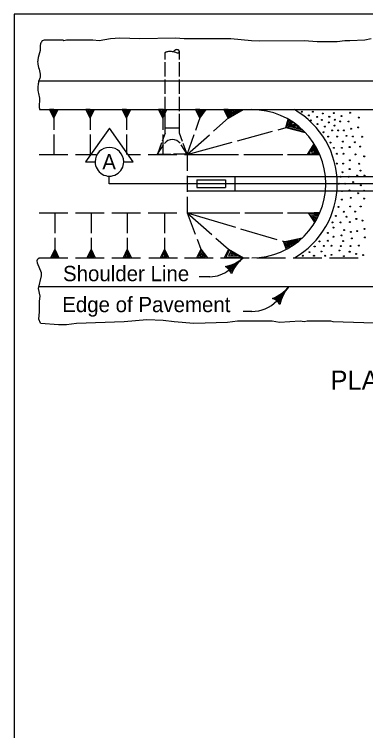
# Model space of a CAD drawing. Extents: x -772 to 772, y -957 to 657.
# Drawn here: x -772 to -405, y -91 to 657 of the extents above; entities that cross this region are included whole.
import ezdxf

# ---------------------------------------------------------------- set-up
doc = ezdxf.new("R2010")
doc.units = 0
for name, color, linetype in [('Default', 7, 'Continuous'), ('dsnCellElements', 7, 'Continuous'), ('dsnStdSection', 7, 'Continuous'), ('Level 2', 7, 'Continuous'), ('Level 3', 7, 'Continuous'), ('Level 4', 7, 'Continuous')]:
    doc.layers.add(name, color=color, linetype=linetype)

msp = doc.modelspace()

# ---------------------------------------------------------------- linework, layer by layer
at = {"layer": 'Default'}
msp.add_line((-746.08, 557.84), (-61.91, 557.84), dxfattribs=at)
for radius, start, end in [(77.5, 0, 90), (89.5, 0, 59.98813), (77.5, 270, 0), (89.5, 300.01187, 360)]:
    msp.add_arc((-524.08, 480.34), radius, start, end, dxfattribs=at)
at = {"layer": 'dsnCellElements'}
msp.add_lwpolyline([(-772.5, 657.5), (-772.5, -657.5), (772.5, -657.5), (772.5, 657.5), (-772.5, 657.5)], dxfattribs=at)
at = {"layer": 'dsnStdSection'}
msp.add_lwpolyline([(-657.96, 503.34), (-647.96, 503.34), (-672.96, 538.34), (-697.96, 503.34), (-687.96, 503.34)], dxfattribs=at)
for start, end in [(0.00083, 179.99917), (179.99917, 0.00083)]:
    msp.add_arc((-672.96, 503.34), 15, start, end, dxfattribs=at)
at = {"layer": 'Level 2'}
for p, q in [((-742.99, 630.31), (-742.83, 630.31)), ((-614.65, 617.56), (-614.79, 617.46)), ((-614.79, 610.4), (-614.79, 617.46)), ((-599.79, 617.83), (-599.78, 618.68)), ((-599.79, 610.4), (-599.79, 617.83)), ((-599.78, 618.71), (-599.78, 618.68)), ((-614.79, 592.4), (-614.79, 607.4)), ((-599.79, 592.4), (-599.79, 607.4)), ((-614.79, 592.4), (-614.79, 592.4)), ((-599.79, 592.4), (-599.79, 592.4)), ((-746.98, 588.25), (-747.03, 587.84)), ((-747.03, 587.84), (-62.6, 587.84)), ((-746.86, 587.68), (-747.03, 587.84)), ((-614.79, 574.4), (-614.79, 589.4)), ((-599.79, 574.4), (-599.79, 589.4)), ((-614.79, 556.4), (-614.79, 571.4)), ((-614.79, 571.4), (-614.79, 571.4)), ((-599.79, 556.4), (-599.79, 571.4)), ((-746.11, 557.99), (-746.08, 557.84)), ((-746.08, 557.84), (-716.58, 557.84)), ((-731.22, 557.84), (-735.72, 557.84)), ((-731.22, 548.84), (-735.72, 557.84)), ((-734.68, 557.44), (-731.19, 550.37)), ((-727.79, 557.3), (-733.59, 557.39)), ((-733.59, 557.39), (-731, 551.69)), ((-729.16, 556.35), (-732.27, 556.64)), ((-732.27, 556.64), (-731.05, 553.29)), ((-730.1, 555.51), (-731.42, 555.84)), ((-731.42, 555.84), (-731, 554.85)), ((-731.22, 557.84), (-731.22, 536.84)), ((-731.22, 548.84), (-731.22, 557.84)), ((-731.22, 557.84), (-726.72, 557.84)), ((-731.22, 548.84), (-726.72, 557.84)), ((-731.19, 550.37), (-727.79, 557.3)), ((-731.05, 553.29), (-730.1, 555.51)), ((-731, 551.69), (-729.16, 556.35)), ((-708.58, 557.84), (-678.58, 557.84)), ((-693.22, 557.84), (-697.72, 557.84)), ((-693.22, 548.84), (-697.72, 557.84)), ((-696.46, 557.27), (-693.21, 550.34)), ((-689.86, 557.18), (-695.19, 557.13)), ((-695.19, 557.13), (-693.21, 552.32)), ((-691.23, 556.43), (-693.87, 556.28)), ((-693.87, 556.28), (-693.16, 553.97)), ((-693.22, 557.84), (-693.22, 536.84)), ((-693.22, 548.84), (-693.22, 557.84)), ((-693.22, 557.84), (-688.72, 557.84)), ((-693.22, 548.84), (-688.72, 557.84)), ((-693.21, 550.34), (-689.86, 557.18)), ((-693.21, 552.32), (-691.23, 556.43)), ((-693.16, 553.97), (-692.41, 555.48)), ((-670.58, 557.84), (-640.58, 557.84)), ((-655.23, 557.84), (-659.73, 557.84)), ((-655.23, 548.84), (-659.73, 557.84)), ((-658.49, 557.2), (-655.26, 550.32)), ((-652.1, 557.16), (-657.33, 557.16)), ((-657.33, 557.16), (-655.3, 552.21)), ((-653.49, 556.4), (-656.01, 556.28)), ((-656.01, 556.28), (-655.21, 554.04)), ((-655.3, 552.21), (-653.49, 556.4)), ((-655.26, 550.32), (-652.1, 557.16)), ((-655.23, 557.84), (-655.23, 536.84)), ((-655.23, 548.84), (-655.23, 557.84)), ((-655.23, 557.84), (-650.73, 557.84)), ((-655.23, 548.84), (-650.73, 557.84)), ((-655.21, 554.04), (-654.43, 555.74)), ((-632.58, 557.84), (-602.58, 557.84)), ((-621.89, 557.84), (-610.2, 557.84)), ((-617.23, 557.84), (-621.73, 557.84)), ((-617.23, 548.84), (-621.73, 557.84)), ((-616.24, 557.84), (-620.74, 557.84)), ((-620.64, 557.28), (-617.25, 550.3)), ((-613.85, 557.23), (-619.51, 557.09)), ((-619.51, 557.09), (-617.29, 551.81)), ((-615.12, 556.33), (-617.95, 556.14)), ((-617.95, 556.14), (-617.15, 553.46)), ((-617.29, 551.81), (-615.12, 556.33)), ((-617.25, 550.3), (-613.85, 557.23)), ((-617.23, 557.84), (-617.23, 536.84)), ((-617.23, 548.84), (-617.23, 557.84)), ((-617.23, 557.84), (-612.73, 557.84)), ((-617.23, 548.84), (-612.73, 557.84)), ((-617.15, 553.46), (-616.54, 555.29)), ((-616.54, 555.29), (-616.3, 555.72)), ((-616.24, 557.84), (-611.74, 557.84)), ((-614.79, 556.4), (-614.79, 556.4)), ((-594.58, 557.84), (-564.58, 557.84)), ((-578.41, 557.84), (-582.91, 557.84)), ((-578.41, 548.84), (-582.91, 557.84)), ((-582.7, 536.45), (-575.29, 557.84)), ((-581.48, 557.16), (-578.37, 550.56)), ((-576.58, 556.88), (-579.97, 557.02)), ((-579.97, 557.02), (-578.56, 553.1)), ((-577.61, 556.03), (-578.75, 556.03)), ((-578.75, 556.03), (-578.6, 554.85)), ((-578.56, 553.1), (-577.61, 556.03)), ((-578.41, 557.84), (-573.91, 557.84)), ((-578.41, 548.84), (-571.62, 557.84)), ((-578.37, 550.56), (-576.58, 556.88)), ((-576.77, 551.92), (-574.74, 556.92)), ((-573.42, 556.88), (-575.63, 553.2)), ((-574.74, 556.92), (-573.42, 556.88)), ((-563.97, 535.35), (-538.62, 557.84)), ((-556.58, 557.84), (-526.58, 557.84)), ((-548.76, 557.84), (-553.26, 557.84)), ((-548.76, 548.84), (-553.26, 557.84)), ((-552.18, 557.23), (-548.64, 549.87)), ((-540.43, 557.28), (-550.95, 557.18)), ((-550.95, 557.18), (-548.5, 551.53)), ((-542.6, 556.48), (-549.53, 556.15)), ((-549.53, 556.15), (-548.17, 553.08)), ((-548.76, 557.84), (-544.26, 557.84)), ((-548.76, 548.84), (-533.1, 557.84)), ((-548.64, 549.87), (-540.43, 557.28)), ((-548.5, 551.53), (-542.6, 556.48)), ((-544.87, 555.63), (-548.26, 555.25)), ((-548.26, 555.25), (-547.84, 554.21)), ((-548.17, 553.08), (-544.87, 555.63)), ((-547.84, 554.21), (-546.71, 554.83)), ((-543.4, 552.47), (-538.36, 557.04)), ((-535.58, 557.18), (-540.34, 554.31)), ((-540.34, 554.31), (-538.17, 556.38)), ((-538.36, 557.04), (-535.58, 557.18)), ((-518.58, 557.84), (-488.58, 557.84)), ((-480.58, 557.84), (-450.58, 557.84)), ((-442.58, 557.84), (-412.58, 557.84)), ((-614.79, 538.4), (-614.79, 553.4)), ((-614.79, 553.4), (-614.79, 553.4)), ((-599.79, 538.4), (-599.79, 553.4)), ((-488.42, 539.18), (-485.93, 547.8)), ((-487.3, 539.49), (-484.86, 547.19)), ((-496.52, 536.91), (-477.35, 542.17)), ((-488.42, 539.18), (-468.1, 533.94)), ((-487.3, 539.49), (-469.19, 535.05)), ((-483.9, 546.61), (-485.75, 540.7)), ((-485.75, 540.7), (-478.4, 542.87)), ((-482.92, 545.04), (-484.15, 542.02)), ((-484.15, 542.02), (-481.51, 543.25)), ((-483.3, 539.57), (-476.7, 541.55)), ((-478.4, 542.87), (-482.92, 545.04)), ((-481.51, 543.25), (-482.31, 543.77)), ((-481.04, 539.29), (-476.6, 540.14)), ((-472.08, 536.74), (-481.04, 539.29)), ((-476.7, 541.55), (-472.08, 536.74)), ((-476.6, 540.14), (-474.81, 538.63)), ((-731.22, 531.84), (-731.22, 510.84)), ((-693.22, 531.84), (-693.22, 510.84)), ((-655.23, 531.84), (-655.23, 510.84)), ((-614.79, 533.4), (-617.81, 525.08)), ((-617.23, 531.84), (-617.23, 510.84)), ((-599.79, 538.4), (-614.79, 538.4)), ((-614.79, 533.4), (-614.79, 538.4)), ((-599.79, 533.4), (-599.79, 538.4)), ((-596.57, 524.56), (-599.79, 533.4)), ((-591.58, 510.84), (-584.3, 531.85)), ((-538.86, 525.3), (-502.22, 535.35)), ((-474.81, 538.63), (-476.65, 539.05)), ((-591.58, 510.84), (-568.21, 531.58)), ((-618.57, 522.99), (-622.83, 511.3)), ((-622.83, 511.3), (-616.48, 520.98)), ((-591.75, 511.3), (-597.77, 520.98)), ((-591.75, 511.3), (-595.84, 522.54)), ((-591.58, 510.84), (-544.58, 523.73)), ((-465.63, 510.95), (-458.89, 522.06)), ((-464.31, 511.68), (-458.29, 520.98)), ((-458.13, 519.68), (-461.73, 513.91)), ((-461.73, 513.91), (-456.79, 516.87)), ((-457.74, 518.39), (-459.38, 516.29)), ((-459.38, 516.29), (-457.86, 517.24)), ((-456.79, 516.87), (-457.74, 518.39)), ((-746.58, 510.84), (-716.58, 510.84)), ((-708.58, 510.84), (-692.6, 510.84)), ((-699.77, 510.84), (-686.83, 510.84)), ((-653.31, 510.84), (-640.58, 510.84)), ((-632.58, 510.84), (-602.58, 510.84)), ((-622.83, 511.3), (-608.83, 511.3)), ((-591.75, 511.3), (-605.75, 511.3)), ((-594.58, 510.84), (-591.58, 510.84)), ((-594.58, 510.84), (-591.58, 510.84)), ((-591.58, 510.84), (-591.58, 493.84)), ((-591.58, 510.84), (-537.9, 510.84)), ((-532.37, 510.84), (-491.68, 510.84)), ((-486.63, 510.84), (-452.83, 510.84)), ((-465.63, 510.95), (-452.62, 510.75)), ((-464.31, 511.68), (-453.22, 511.83)), ((-461.17, 512.71), (-454.34, 512.83)), ((-455.88, 515.43), (-459.02, 513.69)), ((-459.02, 513.69), (-455.81, 513.74)), ((-455.81, 513.74), (-456.14, 514.53)), ((-454.34, 512.83), (-455.88, 515.43)), ((-673.22, 480.34), (-673.22, 488.34)), ((-591.58, 488.84), (-591.58, 471.84)), ((-117.94, 480.34), (-673.22, 480.34)), ((-591.58, 466.84), (-591.58, 449.84)), ((-746.58, 449.84), (-716.58, 449.84)), ((-730.24, 449.84), (-730.24, 428.84)), ((-708.58, 449.84), (-678.58, 449.84)), ((-692.24, 449.84), (-692.24, 428.84)), ((-670.58, 449.84), (-640.58, 449.84)), ((-654.24, 449.84), (-654.24, 428.84)), ((-632.58, 449.84), (-602.58, 449.84)), ((-615.25, 449.84), (-615.25, 428.84)), ((-591.58, 449.84), (-536.54, 449.84)), ((-591.58, 449.84), (-541.02, 434.94)), ((-591.58, 449.84), (-565.82, 427.17)), ((-591.58, 449.84), (-583.18, 427.55)), ((-531.41, 449.84), (-491.68, 449.84)), ((-486.47, 449.84), (-452.83, 449.84)), ((-465.05, 449.83), (-452.54, 450.76)), ((-465.05, 449.83), (-457.93, 439.7)), ((-464.15, 449.39), (-452.97, 449.86)), ((-464.15, 449.39), (-457.59, 440.39)), ((-461.64, 447.51), (-456.09, 444.7)), ((-461.36, 448.74), (-454.06, 448.85)), ((-457.45, 441.9), (-460.49, 446.01)), ((-460.49, 446.01), (-457.1, 444.35)), ((-459.24, 447.71), (-455.53, 448)), ((-455.51, 446.31), (-459.24, 447.71)), ((-457.1, 444.35), (-457.47, 443.38)), ((-456.09, 444.7), (-457.45, 441.9)), ((-455.53, 448), (-455.78, 447.28)), ((-454.06, 448.85), (-455.51, 446.31)), ((-535.85, 433.42), (-497.63, 422.15)), ((-730.24, 423.84), (-730.24, 402.84)), ((-692.24, 423.84), (-692.24, 402.84)), ((-654.24, 423.84), (-654.24, 402.84)), ((-615.25, 423.84), (-615.25, 402.84)), ((-581.28, 422.52), (-577.26, 411.84)), ((-561.5, 423.37), (-548.4, 411.84)), ((-492.21, 420.55), (-479.65, 416.85)), ((-490.65, 419.83), (-471.11, 423.77)), ((-490.65, 419.83), (-488.08, 411.71)), ((-487.11, 419.73), (-472.78, 423.03)), ((-485.32, 419.16), (-475.42, 421.52)), ((-481.45, 419.16), (-478.43, 419.92)), ((-475.79, 419.73), (-479.47, 417.56)), ((-475.42, 421.52), (-479.19, 418.5)), ((-472.78, 423.03), (-475.79, 419.73)), ((-489.09, 418.6), (-487.86, 413.79)), ((-487.86, 413.79), (-481.64, 416.24)), ((-481.64, 416.24), (-487.68, 417.84)), ((-487.68, 417.84), (-487.11, 415.2)), ((-487.11, 415.2), (-484.28, 416.24)), ((-484.28, 416.24), (-486.26, 416.52)), ((-479.47, 417.56), (-485.32, 419.16)), ((-479.19, 418.5), (-481.45, 419.16)), ((-730.24, 411.84), (-734.74, 402.84)), ((-730.17, 410.03), (-733.19, 403.52)), ((-729.6, 408.99), (-731.77, 404.46)), ((-731.77, 404.46), (-728.66, 404.28)), ((-729.56, 406.77), (-730.78, 405.08)), ((-730.78, 405.08), (-729.51, 404.89)), ((-730.24, 411.84), (-730.24, 402.84)), ((-730.24, 411.84), (-725.74, 402.84)), ((-727.29, 403.47), (-729.6, 408.99)), ((-728.66, 404.28), (-729.56, 406.77)), ((-692.24, 411.84), (-696.74, 402.84)), ((-692.21, 410.55), (-695.42, 403.52)), ((-691.69, 409.18), (-693.91, 404.37)), ((-693.91, 404.37), (-690.61, 404.42)), ((-691.6, 407.29), (-692.78, 405.03)), ((-692.78, 405.03), (-691.5, 405.08)), ((-692.24, 411.84), (-692.24, 402.84)), ((-692.24, 411.84), (-687.74, 402.84)), ((-692.24, 411.02), (-692.24, 402.84)), ((-689.19, 403.57), (-691.69, 409.18)), ((-690.61, 404.42), (-691.6, 407.29)), ((-691.5, 405.08), (-691.55, 405.6)), ((-654.24, 411.84), (-658.74, 402.84)), ((-654.42, 409.86), (-656.97, 403.92)), ((-653.85, 408.54), (-655.08, 405.24)), ((-655.08, 405.24), (-652.72, 404.86)), ((-654.24, 411.84), (-654.24, 402.84)), ((-654.24, 411.84), (-649.74, 402.84)), ((-654.24, 411.02), (-654.24, 402.84)), ((-651.21, 403.92), (-653.85, 408.54)), ((-653.67, 406.75), (-653.85, 405.71)), ((-652.72, 404.86), (-653.67, 406.75)), ((-615.25, 411.84), (-619.75, 402.84)), ((-615.43, 409.86), (-617.98, 403.92)), ((-614.87, 408.54), (-616.09, 405.24)), ((-616.09, 405.24), (-613.74, 404.86)), ((-615.25, 411.84), (-615.25, 402.84)), ((-615.25, 411.84), (-610.75, 402.84)), ((-615.25, 411.02), (-615.25, 402.84)), ((-612.23, 403.92), (-614.87, 408.54)), ((-614.68, 406.75), (-614.87, 405.71)), ((-613.74, 404.86), (-614.68, 406.75)), ((-577.26, 411.84), (-581.76, 402.84)), ((-576.83, 410.17), (-579.75, 403.85)), ((-575.89, 408.76), (-577.87, 404.61)), ((-577.87, 404.61), (-574.38, 404.99)), ((-577.26, 411.84), (-570.47, 402.84)), ((-575.89, 406.68), (-576.45, 405.65)), ((-572.3, 403.76), (-575.89, 408.76)), ((-574.38, 404.99), (-575.89, 406.68)), ((-548.4, 411.84), (-552.9, 402.84)), ((-547.5, 410.64), (-550.99, 404.14)), ((-545.9, 409.51), (-548.54, 405.36)), ((-548.54, 405.36), (-539.2, 404.99)), ((-548.4, 411.84), (-532.73, 402.84)), ((-535.52, 403.76), (-545.9, 409.51)), ((-545.43, 407.81), (-545.9, 406.59)), ((-545.9, 406.59), (-543.54, 405.93)), ((-539.2, 404.99), (-545.43, 407.81)), ((-746.84, 402.62), (-746.58, 402.84)), ((-746.58, 402.84), (-716.58, 402.84)), ((-730.24, 402.84), (-734.74, 402.84)), ((-733.19, 403.52), (-727.29, 403.47)), ((-730.24, 402.84), (-725.74, 402.84)), ((-708.58, 402.84), (-678.58, 402.84)), ((-692.24, 402.84), (-696.74, 402.84)), ((-695.42, 403.52), (-689.19, 403.57)), ((-692.24, 402.84), (-687.74, 402.84)), ((-670.58, 402.84), (-640.58, 402.84)), ((-654.24, 402.84), (-658.74, 402.84)), ((-656.97, 403.92), (-651.21, 403.92)), ((-654.24, 402.84), (-649.74, 402.84)), ((-631.59, 402.84), (-601.59, 402.84)), ((-615.25, 402.84), (-619.75, 402.84)), ((-617.98, 403.92), (-612.23, 403.92)), ((-615.25, 402.84), (-610.75, 402.84)), ((-594.58, 402.84), (-564.58, 402.84)), ((-577.26, 402.84), (-581.76, 402.84)), ((-579.75, 403.85), (-572.3, 403.76)), ((-577.26, 402.84), (-572.76, 402.84)), ((-556.58, 402.84), (-526.58, 402.84)), ((-548.4, 402.84), (-552.9, 402.84)), ((-550.99, 404.14), (-535.52, 403.76)), ((-548.4, 402.84), (-543.9, 402.84)), ((-533.1, 402.84), (-547.82, 390.49)), ((-518.58, 402.84), (-488.58, 402.84)), ((-480.58, 402.84), (-450.58, 402.84)), ((-442.58, 402.84), (-412.58, 402.84)), ((-567.89, 383.23), (-578.89, 383.23)), ((-746.69, 372.84), (-59.41, 372.84)), ((-485.48, 372.65), (-497.84, 357.93)), ((-524.07, 346.98), (-533.07, 346.98)), ((-745.04, 334.56), (-744.8, 334.48))]:
    msp.add_line(p, q, dxfattribs=at)
for points in [[(-742.83, 630.31), (-740.86, 630.96), (-721.84, 630.96), (-720.53, 630.31), (-717.91, 630.96), (-690.36, 630.96), (-683.8, 630.31), (-671.99, 632.27), (-662.15, 632.93), (-641.16, 632.27), (-603.77, 632.93), (-594.59, 632.27), (-562.45, 632.27), (-546.05, 632.27), (-524.4, 630.31), (-515.88, 629.65), (-469.3, 630.31), (-455.53, 628.99), (-434.54, 628.99), (-426.67, 630.31), (-421.42, 630.31), (-405.68, 630.96), (-399.12, 632.27)], [(-745.04, 334.56), (-746.68, 338.66), (-746.02, 346.53), (-746.02, 357.68), (-745.53, 362.77), (-747.17, 370.8), (-744.05, 384.09), (-744.22, 387.37), (-748.15, 397.2), (-748.65, 399.99), (-747.99, 401.96), (-746.84, 402.62)], [(-545.23, 388.01), (-546.98, 391.22), (-549.87, 393.49), (-545.25, 394.67), (-539.04, 397.88), (-543.55, 391.86), (-545.06, 388.75), (-546.47, 391.64), (-548.19, 393.23), (-545.15, 394), (-541.64, 395.7), (-543.97, 392.21), (-545.11, 390.31), (-546.78, 392.91), (-543.89, 393.81), (-545.13, 391.87), (-545.82, 392.65), (-544.83, 393.06)], [(-494.85, 355.94), (-497.13, 358.79), (-500.38, 360.54), (-496.03, 362.5), (-490.47, 366.74), (-493.87, 360.02), (-494.81, 356.69), (-496.71, 359.3), (-498.67, 360.56), (-495.82, 361.85), (-492.65, 364.14), (-494.34, 360.3), (-495.14, 358.22), (-497.24, 360.49), (-494.54, 361.88), (-495.42, 359.75), (-496.25, 360.41), (-495.34, 360.98)], [(-744.8, 334.48), (-726.43, 333.16), (-717.91, 333.16), (-707.41, 334.48), (-657.56, 336.44), (-633.95, 338.41), (-616.89, 337.76), (-605.09, 336.44), (-584.75, 334.48), (-549.33, 335.79), (-538.83, 337.1), (-502.76, 337.1), (-494.89, 335.79), (-473.24, 337.1), (-469.3, 336.44), (-466.02, 337.1), (-441.75, 337.1), (-439.13, 336.44), (-395.84, 335.13), (-378.78, 334.48), (-376.82, 333.82), (-363.7, 333.82), (-341.39, 334.48)]]:
    msp.add_lwpolyline(points, dxfattribs=at)
for centre in [(-471.67, 555.65), (-460.14, 555.65), (-449.74, 553.82), (-438.17, 554.31), (-421.2, 554.69), (-464.22, 551.85), (-462.11, 546.64), (-455.51, 550.3), (-450.59, 547.07), (-442.86, 550.44), (-437.24, 547.35), (-430.06, 551.1), (-412.15, 549.6), (-455.22, 542.84), (-447.5, 540.17), (-443.42, 544.53), (-437.38, 541.16), (-431.38, 545.63), (-422.71, 545.45), (-412.53, 539.22), (-448.9, 534.26), (-440.05, 536.09), (-433.58, 536.09), (-427.61, 536.21), (-420.07, 537.89), (-444.07, 529.62), (-434.71, 529.62), (-428.56, 524.51), (-425.05, 530.48), (-418.18, 529.79), (-416.11, 523.74), (-408.56, 529.6), (-441.73, 523.42), (-438.08, 517.94), (-429.65, 517.94), (-421.58, 518.67), (-410.45, 519.23), (-434.94, 511.69), (-428.18, 511.69), (-415.54, 511.12), (-406.3, 509.05), (-435.13, 501.5), (-428.37, 501.5), (-421.39, 504.9), (-411.58, 501.32), (-421.58, 495.66), (-410.26, 494.13), (-431.09, 487.74), (-429.12, 492.45), (-422.52, 487.74), (-413.85, 488.87), (-406.11, 488.87), (-433.06, 480.38), (-426.29, 480.38), (-417.99, 482.08), (-409.88, 478.87), (-429.5, 472.65), (-421.77, 473.4), (-406.49, 473.01), (-429.69, 463.78), (-420.45, 465.67), (-412.71, 470.39), (-406.49, 464.92), (-420.96, 456.59), (-410.07, 456.6), (-433.12, 456.21), (-427.8, 451.15), (-415.92, 451.34), (-436.07, 446.74), (-424.79, 445.9), (-414.6, 443.58), (-408.19, 441.91), (-439.57, 440), (-438.6, 434.49), (-431.01, 440), (-431.01, 440), (-421.39, 440.4), (-444.28, 429.01), (-430.06, 426.37), (-427.42, 431.91), (-420.19, 430), (-413.66, 430.97), (-405.92, 433.21), (-453.14, 420.15), (-444.28, 420.85), (-438.6, 424.93), (-428.37, 420.41), (-419.31, 423.24), (-405.55, 424.37), (-458.2, 414.8), (-448.78, 415.36), (-440.63, 415.59), (-430.91, 415.26), (-420.82, 415.29), (-411.96, 415.69), (-470.7, 405.09), (-463.68, 408.89), (-458.9, 405.09), (-451.17, 409.59), (-447.09, 405.09), (-440.63, 406.08), (-432.33, 410.6), (-427.61, 404.69), (-421.58, 409.28), (-414.82, 406.99), (-407.62, 405.89)]:
    msp.add_circle(centre, 0.5, dxfattribs=at)
for centre, radius, start, end in [((-607.09, 516.06), 10.58, 38.65393, 141.6575), ((-560.41, 435.4), 42.5, 281.92751, 310), ((-505.78, 370.29), 42.5, 130, 158.07249), ((-567.81, 414.37), 31.14, 269.84624, 309.93523), ((-560.39, 379.94), 16.42, 22.26665, 57.73335), ((-518.04, 399.97), 42.5, 291.92751, 320), ((-452.92, 345.33), 42.5, 140, 168.07249), ((-508.39, 345.35), 16.42, 32.26665, 67.73335), ((-523.84, 383.33), 36.36, 269.64484, 315.66676)]:
    msp.add_arc(centre, radius, start, end, dxfattribs=at)
for points in [[(-742.99, 630.31), (-744.96, 626.7), (-745.61, 619.82), (-747.91, 609.98), (-747.91, 605.39), (-745.61, 591.45), (-746.98, 588.25)], [(-614.65, 617.56), (-613.88, 618.1), (-613.13, 618.43), (-612.01, 618.68), (-609.48, 618.89), (-608.28, 618.86), (-606.22, 618.51), (-603.95, 617.77), (-602.22, 617.27), (-601.29, 617.19), (-600.76, 617.3), (-600.1, 617.83), (-599.83, 618.33), (-599.78, 618.71), (-599.94, 619.37), (-600.1, 619.66), (-600.46, 619.98), (-600.55, 620.06), (-601.32, 620.46), (-602.35, 620.56), (-603.73, 620.25), (-604.7, 619.71), (-605.2, 619.31), (-605.82, 618.62), (-605.97, 618.46)], [(-746.86, 587.68), (-747.58, 584.07), (-747.58, 576.2), (-746.11, 569.96), (-746.6, 562.09), (-746.11, 557.99)]]:
    msp.add_spline(points, degree=3, dxfattribs=at)
at = {"layer": 'Level 4'}
for p, q in [((-591.58, 487.84), (-161.58, 487.84)), ((-541.58, 487.84), (-541.58, 472.84)), ((-581.58, 484.34), (-581.58, 476.34)), ((-581.58, 484.34), (-551.58, 484.34)), ((-551.58, 484.34), (-551.58, 476.34)), ((-591.58, 472.84), (-161.58, 472.84)), ((-581.58, 476.34), (-551.58, 476.34))]:
    msp.add_line(p, q, dxfattribs=at)

# ---------------------------------------------------------------- texts
at = {"layer": 'Level 3'}
for s, height, p in [('A', 16, (-680.43, 495.34)), ('Shoulder Line', 16, (-721.55, 378.54)), ('Edge of Pavement', 16, (-722.38, 346.16)), ('PLAN', 20, (-441.73, 265.1))]:
    msp.add_text(s, height=height, dxfattribs=at).set_placement(p)

doc.saveas('drawing.dxf')
